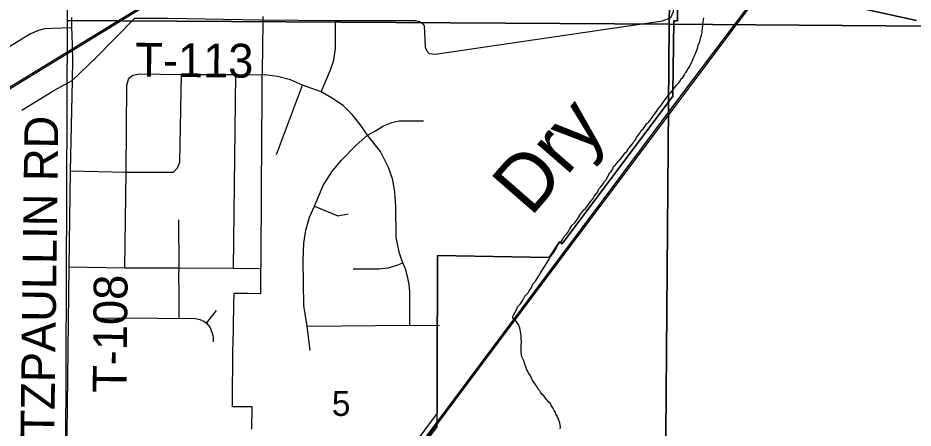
# Model space of a CAD drawing. Extents: x -7.3 to 34, y 0 to 22.
# Drawn here: x 3.68 to 5.185, y 18.004 to 18.693 of the extents above; entities that cross this region are included whole.
import ezdxf

# ---------------------------------------------------------------- set-up
doc = ezdxf.new("R2010")
doc.units = 0
for name, color, linetype in [('GM_X_City_Street', 7, 'Continuous'), ('GM_X_Corporation', 7, 'Continuous'), ('GM_X_Minor_River', 7, 'Continuous'), ('GM_X_Minor_River_Text', 7, 'Continuous'), ('GM_X_Rail_Line', 7, 'Continuous'), ('GM_X_Section_Text', 7, 'Continuous'), ('GM_X_Township_Road', 7, 'Continuous'), ('GM_X_Township_Road_Text', 7, 'Continuous')]:
    doc.layers.add(name, color=color, linetype=linetype)

msp = doc.modelspace()

# ---------------------------------------------------------------- linework, layer by layer
at = {"layer": 'GM_X_City_Street'}
msp.add_line((4.115, 18.4641), (4.1585, 18.5803), dxfattribs=at)
for points in [[(4.0888, 18.6903), (4.2143, 18.6891), (4.3307, 18.6892), (4.3488, 18.6889), (4.3552, 18.6875), (4.36, 18.6844), (4.363, 18.6798), (4.3646, 18.6446), (4.3672, 18.6384), (4.3717, 18.6335), (4.3814, 18.6325), (4.7635, 18.6886), (4.7779, 18.694), (4.7824, 18.7039), (4.7833, 18.7192), (4.7846, 18.7753)], [(4.1898, 18.5693), (4.2057, 18.6061), (4.2111, 18.6226), (4.2143, 18.6419), (4.2143, 18.6891)], [(4.3392, 18.177), (4.339, 18.2333), (4.3379, 18.2457), (4.3359, 18.2567), (4.332, 18.2717), (4.3272, 18.282), (4.3246, 18.2898), (4.3214, 18.3), (4.3182, 18.3136), (4.3162, 18.3252), (4.3158, 18.3773), (4.3141, 18.4007), (4.3104, 18.4213), (4.3033, 18.4422), (4.2895, 18.469), (4.2681, 18.4966), (4.2554, 18.5145), (4.2423, 18.5309), (4.2275, 18.5457), (4.2103, 18.5574), (4.1898, 18.5693), (4.1585, 18.5803), (4.1387, 18.5891), (4.1164, 18.5951), (4.0953, 18.5979)], [(4.1718, 18.1345), (4.1663, 18.1755), (4.1611, 18.2105), (4.16, 18.2866), (4.1611, 18.315), (4.1643, 18.3366), (4.1705, 18.3585), (4.1786, 18.3773), (4.1934, 18.4117), (4.2079, 18.4348), (4.2241, 18.4545), (4.249, 18.4793), (4.2681, 18.4966), (4.2812, 18.5037), (4.2949, 18.5121), (4.309, 18.5177), (4.321, 18.5202), (4.3618, 18.5207)], [(4.1786, 18.3773), (4.218, 18.3611), (4.2357, 18.364)], [(4.244, 18.2719), (4.2872, 18.2719), (4.3024, 18.2735), (4.3159, 18.2774), (4.3272, 18.282)], [(4.1663, 18.1755), (4.3392, 18.177), (4.3888, 18.1769)]]:
    msp.add_lwpolyline(points, dxfattribs=at)
at = {"layer": 'GM_X_Corporation'}
for points in [[(3.767, 19.7044), (4.7904, 19.7043), (4.7747, 18.6827), (3.7636, 18.6887)], [(4.7904, 19.7043), (5.7957, 19.6954), (5.7942, 18.6751), (4.7747, 18.6827)], [(3.7636, 18.6887), (4.7747, 18.6827), (4.7683, 17.8564), (4.7527, 17.8336), (4.7133, 17.8325), (4.6796, 17.8298), (4.6564, 17.8265), (4.6115, 17.8156), (4.5897, 17.8074), (4.571, 17.7971), (4.5456, 17.7791), (4.5329, 17.7676), (4.5122, 17.7392), (4.5024, 17.7194), (4.4999, 17.7088), (4.5002, 17.6706), (4.4977, 17.6589), (3.7599, 17.6756)]]:
    msp.add_lwpolyline(points, close=True, dxfattribs=at)
for points in [[(4.3205, 17.9202), (4.385, 18.0067), (4.3851, 18.0296), (4.3851, 18.1309), (4.3853, 18.1726), (4.3853, 18.182), (4.3854, 18.2019), (4.3854, 18.2104), (4.3854, 18.2209), (4.3854, 18.2294), (4.3855, 18.243), (4.3855, 18.2483), (4.3856, 18.2684), (4.3856, 18.2942), (4.5107, 18.2922), (4.5732, 18.2911), (4.5907, 18.317), (4.5953, 18.3136), (4.781, 18.5618), (4.7811, 18.5668), (4.7829, 18.6883), (4.7892, 18.6882), (4.7889, 18.7146)], [(4.7889, 18.7146), (4.7892, 18.6882), (4.7829, 18.6883), (4.7811, 18.5668), (4.781, 18.5618), (4.7809, 18.5616), (4.5953, 18.3136), (4.5907, 18.317), (4.5732, 18.2911), (4.5107, 18.2922), (4.3856, 18.2942), (4.3856, 18.2684), (4.3855, 18.2483), (4.3855, 18.243), (4.3854, 18.2294), (4.3854, 18.2209), (4.3854, 18.2104), (4.3854, 18.2019), (4.3853, 18.182), (4.3853, 18.1726), (4.3851, 18.1309), (4.3851, 18.0296), (4.3212, 17.9438)], [(5.075, 18.7141), (5.1908, 18.6891)], [(5.1908, 18.6891), (5.075, 18.7141)], [(4.0736, 18.0024), (4.074, 18.0402), (4.0409, 18.0402), (4.041, 18.0547), (4.0411, 18.0639), (4.0413, 18.0821), (4.0415, 18.0999), (4.0416, 18.1165), (4.0418, 18.1309), (4.0418, 18.133), (4.0421, 18.1496), (4.0425, 18.1689), (4.0426, 18.1755), (4.0432, 18.2112), (4.0436, 18.2308), (4.0448, 18.2308), (4.0666, 18.2307), (4.0886, 18.2305), (4.0889, 18.2682), (4.089, 18.2777), (4.0891, 18.3014), (4.0893, 18.3156), (4.0894, 18.3274), (4.0894, 18.3351), (4.0896, 18.3552), (4.0897, 18.3753), (4.0898, 18.3954), (4.0898, 18.4155), (4.0899, 18.4356), (4.0901, 18.4557), (4.0901, 18.4618), (4.0902, 18.4757), (4.0904, 18.4958), (4.0905, 18.5057), (4.0905, 18.5159), (4.0907, 18.5319), (4.0907, 18.536), (4.0908, 18.5521), (4.0909, 18.5561), (4.0909, 18.5671), (4.0911, 18.594), (4.0912, 18.6035), (4.0921, 18.6449), (4.0925, 18.6861), (4.0925, 18.6958)], [(5.21, 17.8036), (5.1843, 17.825), (5.1618, 17.8341), (5.1467, 17.836), (5.0612, 17.8399), (4.8592, 17.8372), (4.7861, 17.8349), (4.7775, 17.84), (4.7683, 17.8564), (4.7747, 18.6827), (5.7942, 18.6751)]]:
    msp.add_lwpolyline(points, dxfattribs=at)
at = {"layer": 'GM_X_Minor_River'}
for points in [[(4.7257, 18.4995), (4.7277, 18.504), (4.7311, 18.507), (4.7343, 18.5111), (4.7366, 18.5156), (4.7409, 18.519), (4.7467, 18.5268), (4.7495, 18.5309), (4.7534, 18.5362), (4.7553, 18.5388), (4.7593, 18.544), (4.762, 18.5474), (4.7667, 18.5538), (4.7698, 18.5583), (4.7718, 18.5609), (4.7741, 18.5635), (4.7757, 18.5661), (4.7784, 18.5687), (4.7819, 18.5728), (4.7846, 18.5762), (4.7866, 18.5799), (4.7901, 18.5829), (4.7928, 18.5867), (4.7948, 18.5904), (4.7979, 18.5934), (4.8002, 18.5964), (4.8014, 18.5998), (4.8038, 18.6024), (4.8077, 18.6088), (4.8097, 18.6121), (4.8124, 18.6182), (4.8136, 18.6208), (4.816, 18.6264), (4.8176, 18.6298), (4.8204, 18.6362), (4.8212, 18.6389), (4.8224, 18.6419), (4.8233, 18.6449), (4.8245, 18.6491), (4.8257, 18.6517), (4.8269, 18.6562), (4.8282, 18.6612), (4.8294, 18.6646), (4.8302, 18.6687), (4.8307, 18.6714), (4.8311, 18.6752), (4.8317, 18.6824), (4.8321, 18.6869), (4.833, 18.6934)], [(4.5387, 18.0964), (4.538, 18.099), (4.5357, 18.1021), (4.534, 18.1075), (4.5321, 18.111), (4.5311, 18.1163), (4.5297, 18.1194), (4.5275, 18.124), (4.5268, 18.1274), (4.5261, 18.1305), (4.5262, 18.1343), (4.5263, 18.1369), (4.5264, 18.1415), (4.5264, 18.1445), (4.5265, 18.1472), (4.5266, 18.1506), (4.5263, 18.1541), (4.5263, 18.1567), (4.526, 18.1594), (4.5257, 18.1628), (4.525, 18.1666), (4.5243, 18.1697), (4.5233, 18.1739), (4.5218, 18.1781), (4.5196, 18.1812), (4.517, 18.1843), (4.5148, 18.187), (4.5122, 18.189), (4.5123, 18.1916), (4.5139, 18.195), (4.5154, 18.198), (4.5182, 18.2029), (4.5202, 18.2078), (4.5245, 18.2123), (4.5264, 18.2149), (4.5292, 18.2194), (4.5324, 18.2262), (4.5378, 18.2318), (4.5398, 18.2351), (4.5429, 18.2392), (4.5457, 18.246), (4.5504, 18.2509), (4.5519, 18.2539), (4.5559, 18.2603), (4.5582, 18.264), (4.5629, 18.2711), (4.5649, 18.2749), (4.5688, 18.2809), (4.5732, 18.288), (4.5751, 18.2922), (4.579, 18.2966), (4.5814, 18.3004), (4.5853, 18.306), (4.5881, 18.312), (4.5927, 18.3165), (4.5963, 18.3214), (4.5986, 18.3262), (4.6025, 18.33), (4.6057, 18.3348), (4.6072, 18.3379), (4.6116, 18.3446), (4.6162, 18.3491), (4.6193, 18.3532), (4.6217, 18.3562), (4.6248, 18.3622), (4.6283, 18.3667), (4.6315, 18.3708), (4.6342, 18.3734), (4.6365, 18.376), (4.6393, 18.3801), (4.6432, 18.3854), (4.6471, 18.3902), (4.6494, 18.3943), (4.6533, 18.3988), (4.6553, 18.4014), (4.6569, 18.406), (4.66, 18.4093), (4.6639, 18.4146), (4.6663, 18.4183), (4.6694, 18.4217), (4.6706, 18.4251), (4.6725, 18.4277), (4.6745, 18.433), (4.6772, 18.4356), (4.68, 18.4397), (4.6816, 18.4435), (4.6847, 18.4468), (4.6894, 18.452), (4.6921, 18.455), (4.6956, 18.4587), (4.6983, 18.4629), (4.7011, 18.4666), (4.7038, 18.4692), (4.7073, 18.4748), (4.7108, 18.4786), (4.7139, 18.4823), (4.7155, 18.4857), (4.7182, 18.4883), (4.7198, 18.4924), (4.7225, 18.495), (4.7257, 18.4995)], [(4.592, 18.0032), (4.5921, 18.0066), (4.5918, 18.0097), (4.5911, 18.0131), (4.59, 18.0158), (4.5893, 18.0185), (4.5879, 18.0215), (4.5868, 18.0242), (4.5846, 18.0277), (4.5839, 18.0304), (4.5817, 18.0338), (4.5795, 18.0381), (4.5766, 18.0423), (4.5755, 18.0454), (4.5729, 18.0477), (4.5707, 18.0504), (4.5684, 18.0531), (4.5659, 18.0562), (4.564, 18.0589), (4.5614, 18.0609), (4.5588, 18.0644), (4.5574, 18.0671), (4.5548, 18.0698), (4.553, 18.0736), (4.5496, 18.0783), (4.5463, 18.0829), (4.5445, 18.0856), (4.5427, 18.091), (4.5405, 18.0937), (4.5387, 18.0964)]]:
    msp.add_lwpolyline(points, dxfattribs=at)
at = {"layer": 'GM_X_Rail_Line'}
for points in [[(2.7405, 18.0079), (3.3109, 18.3572), (4.0313, 18.798), (4.702, 19.2088), (4.7774, 19.2546), (4.9109, 19.336), (5.2623, 19.5511), (5.5045, 19.6986), (5.5533, 19.7292), (5.593, 19.7558), (5.6212, 19.7759), (5.6461, 19.795), (5.6821, 19.8246), (5.7051, 19.845), (5.7282, 19.867), (5.7473, 19.8866), (5.7663, 19.9054), (5.7919, 19.9343), (5.8126, 19.9584), (5.8283, 19.9791), (5.855, 20.0143)], [(3.6345, 17.0151), (3.985, 17.4802), (4.3732, 17.9988), (4.5251, 18.2021), (4.7981, 18.5667), (5.0774, 18.9371), (5.1565, 19.0428), (5.1846, 19.0805), (5.2002, 19.101), (5.5499, 19.5711), (5.7863, 19.8846), (5.8776, 20.0139)], [(3.636, 17.0139), (3.9865, 17.479), (4.3757, 17.998), (4.5264, 18.1998), (4.796, 18.5597), (5.0789, 18.9359), (5.158, 19.0417), (5.1862, 19.0793), (5.2017, 19.0998), (5.5529, 19.5699), (5.7879, 19.8835), (5.8792, 20.0128)], [(2.7702, 18.0262), (2.7976, 18.0458), (3.3096, 18.3593), (4.03, 18.8001), (4.7007, 19.211), (4.7761, 19.2568), (4.8865, 19.324), (4.9045, 19.332)]]:
    msp.add_lwpolyline(points, dxfattribs=at)
at = {"layer": 'GM_X_Township_Road'}
for p, q in [((4.0427, 18.2731), (4.0465, 18.5983)), ((3.9512, 18.2735), (3.951, 18.3542)), ((3.9971, 18.1806), (4.0142, 18.202))]:
    msp.add_line(p, q, dxfattribs=at)
for points in [[(3.7707, 18.6939), (3.7706, 18.6764), (3.7709, 18.6667)], [(3.7713, 18.5881), (3.8113, 18.6262), (3.877, 18.6927)], [(3.877, 18.6927), (3.9326, 18.693), (4.0888, 18.6903)], [(3.7706, 18.6764), (3.7386, 18.6753), (3.7254, 18.6747), (3.715, 18.6724), (3.7015, 18.6664), (3.6604, 18.6411), (3.5517, 18.575)], [(3.7709, 18.6667), (3.7719, 18.6229), (3.7713, 18.5881), (3.7683, 18.4365), (3.7659, 18.2752), (3.7598, 17.7637)], [(3.8669, 18.5921), (3.8734, 18.5972), (3.8847, 18.5996), (3.9553, 18.5982), (4.0465, 18.5983), (4.0953, 18.5979)], [(3.9416, 18.4344), (3.9488, 18.4413), (3.9526, 18.451), (3.9553, 18.5982)], [(3.6868, 18.5381), (3.7406, 18.5712), (3.7713, 18.5881)], [(3.8599, 18.2737), (3.8622, 18.4344), (3.8632, 18.5802), (3.8669, 18.5921)], [(3.7683, 18.4365), (3.8622, 18.4344), (3.9416, 18.4344)], [(3.7659, 18.2752), (3.8599, 18.2737), (3.9512, 18.2735), (4.0427, 18.2731), (4.0862, 18.2726)], [(3.9512, 18.1886), (3.9514, 18.2305), (3.951, 18.262), (3.9512, 18.2735)], [(3.8124, 18.1896), (3.9155, 18.1887), (3.9776, 18.1886), (3.9815, 18.1881), (3.9861, 18.1867), (3.9899, 18.1851), (3.9937, 18.1834), (3.9971, 18.1806), (4.0005, 18.1769), (4.0033, 18.1734), (4.0054, 18.1684), (4.007, 18.1639), (4.0079, 18.1597), (4.0084, 18.1567), (4.0083, 18.1523), (4.0083, 18.1491)]]:
    msp.add_lwpolyline(points, dxfattribs=at)

# ---------------------------------------------------------------- texts
at = {"layer": 'GM_X_Minor_River_Text'}
msp.add_text('Dry', height=0.09473, rotation=49.0076, dxfattribs=at).set_placement((4.5423, 18.3578))
at = {"layer": 'GM_X_Section_Text'}
msp.add_text('5', height=0.0419, rotation=0, dxfattribs=at).set_placement((4.208, 18.0248))
at = {"layer": 'GM_X_Township_Road_Text'}
for s, height, rotation, p in [('T-113', 0.05682, 359.4423, (3.8774, 18.5948)), ('MARTZPAULLIN RD', 0.056818, 89.2718, (3.7393, 17.8194)), ('T-108', 0.05682, 89.4386, (3.8628, 18.0632))]:
    msp.add_text(s, height=height, rotation=rotation, dxfattribs=at).set_placement(p)

doc.saveas('drawing.dxf')
